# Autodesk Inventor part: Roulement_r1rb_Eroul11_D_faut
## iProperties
Created: 2011-10
Part Number: Roulement_r1rb_Eroul11_D_faut
Document SubType Name: Modeling
Designer: Bruno
Author: Bruno
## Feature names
1. Base1
